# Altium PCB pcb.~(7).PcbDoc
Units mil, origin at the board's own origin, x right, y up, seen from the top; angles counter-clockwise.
Board outline 2165 x 2075 mil, 2 copper layers (Top Layer, Bottom Layer); 12 components, 10 nets, 37 pads, 0 vias.
Unrouted connection lines stored in the file: 25.
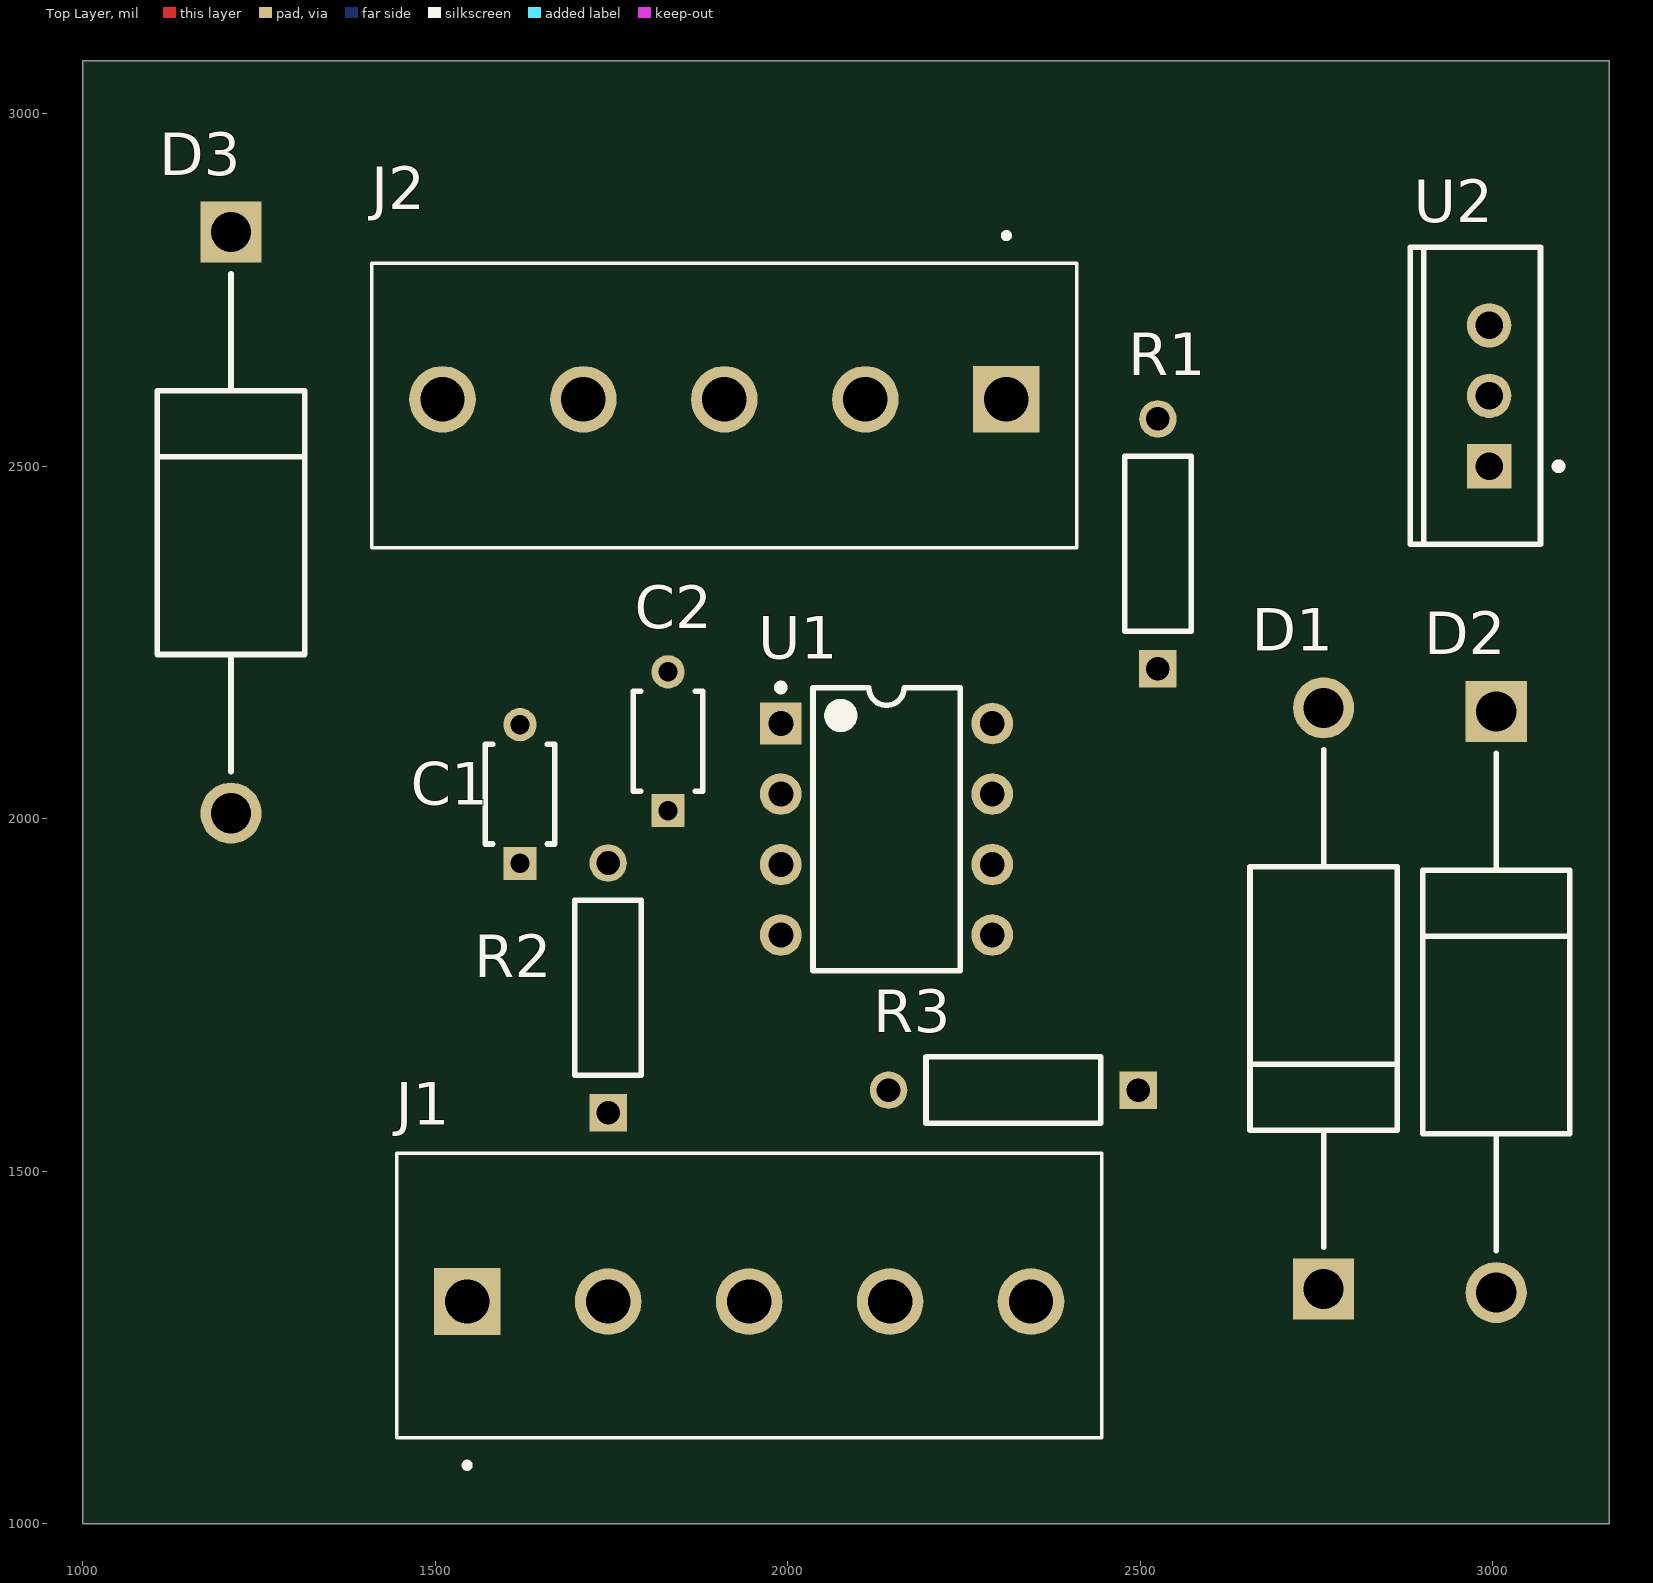
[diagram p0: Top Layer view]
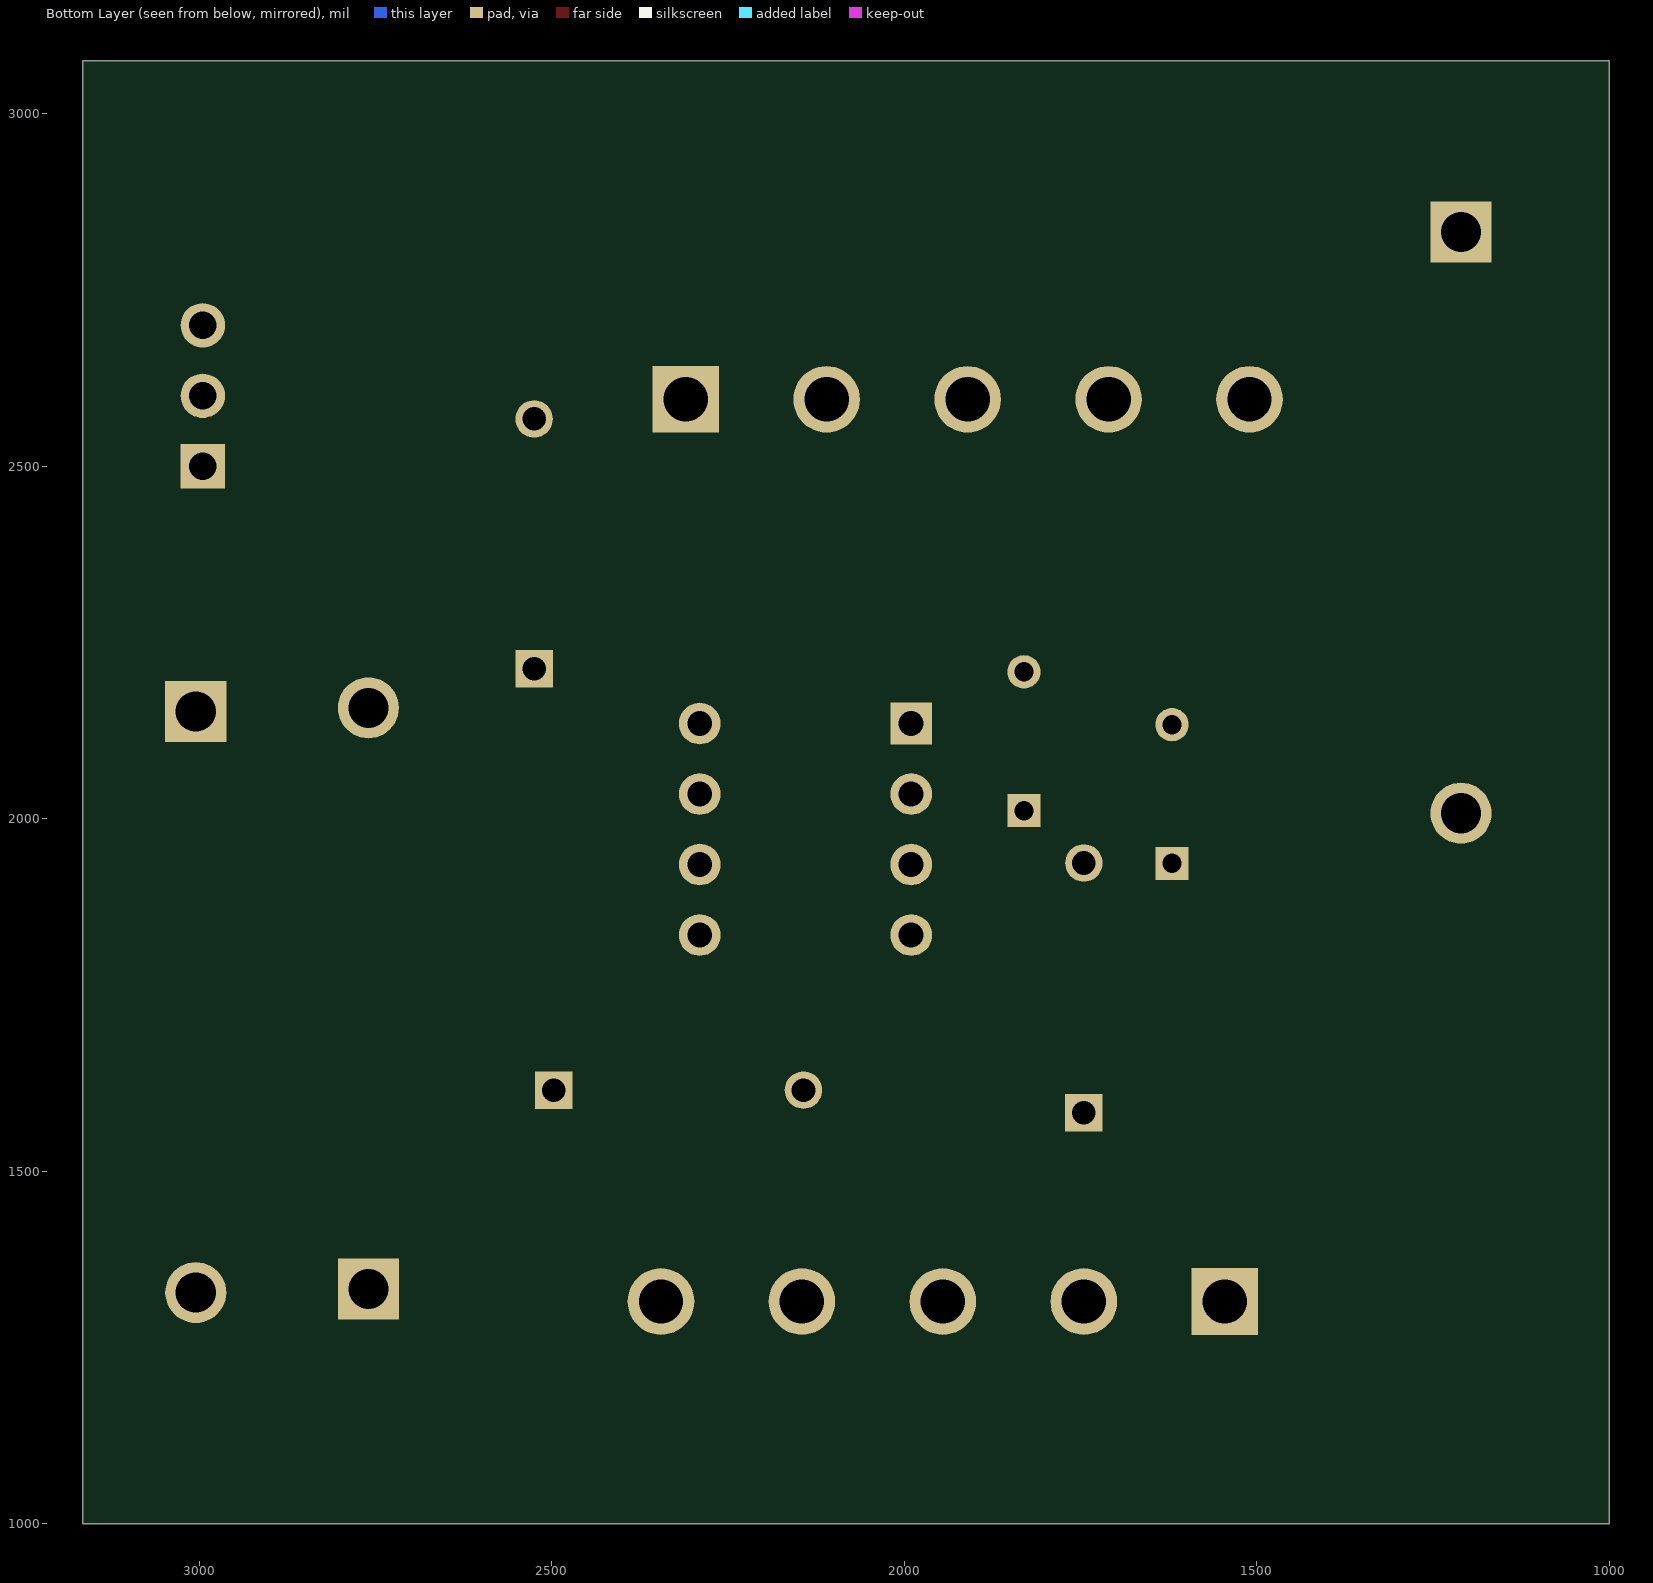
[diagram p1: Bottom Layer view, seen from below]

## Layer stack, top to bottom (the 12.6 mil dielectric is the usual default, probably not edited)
Top Solder: solder mask 0.4, Solder Resist, Dk 3.5
Top Layer: signal copper 1.4
Dielectric 1: dielectric 12.6, FR-4, Dk 4.8
Bottom Layer: signal copper 1.4
Bottom Solder: solder mask 0.4, Solder Resist, Dk 3.5

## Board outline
1000,1000 3165,1000 3165,3075 1000,3075

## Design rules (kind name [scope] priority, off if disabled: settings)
Clearance [All] p1: gap=10 ignorepadtopadclearanceinfootprint=FALSE except(0: Arc-Hole Track-Hole SMDPad-Hole THPad-Hole Via-Hole Fill-Hole Poly-Hole Region-Hole Text-Hole)
PolygonConnect [All] p1: connectstyle=Relief reliefconductorwidth=10 reliefentries=4 polygonreliefangle="90 Angle" airgapwidth=10
RoutingVias [All] p1: holewidth=30 width=50 viastyle="Through Hole" minholewidth=26 minwidth=36 maxholewidth=50 maxwidth=70
SolderMaskExpansion [All] p1: expansion=4 istentingtop=FALSE
Width [All] p1: maxlimit=50 minlimit=15 preferedwidth=35
30 further rules are at their usual default settings.

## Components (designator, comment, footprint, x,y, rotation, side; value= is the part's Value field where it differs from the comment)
C1 "RCER71H103K0K1H03B" FP-RCE0K1-MFG 1620,2035 r90 top
C2 "RCER71H103K0K1H03B" FP-RCE0K1-MFG 1830,2110 r90 top
D1 "1N5408G-T" FP-DO-201AD-MFG 2760,1745 r90 top
D2 "1N5408G-T" FP-DO-201AD-MFG 3005,1740 r270 top
D3 "1N5408G-T" FP-DO-201AD-MFG 1210,2420 r270 top
J1 "TB007-508-05BE" CUI_TB007-508-05BE 1545,1315 r0 top
J2 "TB007-508-05BE" CUI_TB007-508-05BE 2310,2595 r180 top
R1 "MFR-25FBF52-1K" RESA60-630X240 2525,2390 r90 top
R2 "MFR-25FBF52-1K" RESA60-630X240 1745,1760 r90 top
R3 "MFR-25FBF52-1K" RESA60-630X240 2320,1615 r180 top
U1 "NE555P" P0008A 2140,1985 r0 top
U2 "LM395T/NOPB" NDE0003A 2995,2600 r90 top

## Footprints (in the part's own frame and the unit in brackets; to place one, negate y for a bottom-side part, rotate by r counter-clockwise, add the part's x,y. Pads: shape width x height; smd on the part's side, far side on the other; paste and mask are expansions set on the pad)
CUI_TB007-508-05BE [mm]
  rect 2.4x2.4 hole 1.6: 1(0,0)
  round 2.4 hole 1.6: 2(5.08,0) 3(10.16,0) 4(15.24,0) 5(20.32,0)
  silkscreen extent -2.54,-6 22.86,5.35
FP-DO-201AD-MFG [mm]
  rect 2.2x2.2 hole 1.45 paste-1000 mask+0: 1(-10.47,0)
  round 2.2 hole 1.45 paste-1000 mask+0: 2(10.47,0)
  silkscreen extent -8.97,-2.65 8.97,2.65, body extent -11.67,-2.75 11.67,2.75, height 0.25
FP-RCE0K1-MFG [mm]
  rect 1.2x1.2 hole 0.7 paste-1000 mask+0: 1(-2.5,0)
  round 1.2 hole 0.7 paste-1000 mask+0: 2(2.5,0)
  silkscreen extent -1.8,-1.25 1.8,1.25, body extent -3.2,-1.35 3.2,1.35, height 0.25
NDE0003A [mm] "FM, 3-Leads, Body 10.7x4.7mm, Pitch 2.54mm"
  rect 1.6x1.6 hole 1: 1(-2.54,0)
  round 1.6 hole 1: 2(0,0) 3(2.54,0)
  silkscreen extent -5.35,-2.63 5.35,2.85, body extent -5.4,-1.9 5.4,2.9, height 19.4
P0008A [mm] "DIP, 8-Leads, Body 10.15x6.6mm, Pitch 2.54mm"
  rect 1.5x1.5 hole 0.9: 1(-3.81,3.81)
  round 1.5 hole 0.9: 2(-3.81,1.27) 3(-3.81,-1.27) 4(-3.81,-3.81) 5(3.81,-3.81) 6(3.81,-1.27) 7(3.81,1.27) 8(3.81,3.81)
  silkscreen extent -3.93,-5.1 2.65,5.23, body extent -3.95,-5.07 3.95,5.07, height 5.08
RESA60-630X240 [mm] "Axial Resistor, 2-Leads, Dia 2.4mm, Body Length 6.3mm"
  rect 1.35x1.35 hole 0.85: 1(-4.5,0)
  round 1.35 hole 0.85: 2(4.5,0)
  silkscreen extent -3.15,-1.2 3.15,1.2, body extent -3.15,-1.2 3.15,1.2, height 2.4

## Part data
C1 C2: library part CMP-06035-044411-1, "Cap Ceramic 10nF 50V X7R ±10% Radial 5mm +125°C Automotive Bulk", Capacitance=10nF, Case/Package=Radial, Dielectric=X7R, Max Operating Temperature=125°C, Min Operating Temperature=-55°C, Package Quantity=500, Ratings=AEC-Q200, Resistor Type=Ceramic, Tolerance=10%, Voltage Rating=50V
D1 D2 D3: library part CMP-12791-000058-1, "DIODE GEN PURP 1KV 3A DO201AD", Average Rectified Current=3A, Capacitance=40pF, Case/Package=DO-201AD, Forward Voltage=1.1V, Max Operating Temperature=150°C, Max Repetitive Reverse Voltage (Vrrm)=1kV, Max Reverse Current=5uA, Max Surge Current=125A, Min Operating Temperature=-65°C, Package Quantity=1200
J1 J2: Package=None
R1 R2 R3: library part CMP-1659-00075-1, "Axial Resistor, 1 KOhm, +/- 1%, 250 mW, -55 to 155 degC, 2-Pin THD, RoHS, Bulk", Case\Package=Axial, Max Operating Temperature="155 degC", Min Operating Temperature="-55 degC", Package Quantity=200, Power Rating="250 mW", Resistance="10 kohm", Tolerance=1%, Voltage Rating="250 V"
U1: library part CMP-2000-04954-1, "Precision Timer, 4.5 to 16 V, 0 to 70 degC, 8-Pin DIP, Pb-Free, Tube", Manufacturer=TexasInstruments, Maximum High Level Output Current=-200mA, Maximum Low Level Output Current=200mA, Operating Supply Voltage=5, Package=8PDIP, Package Description="8-Pin Double In-line Package, Body 9.59 x 6.35 mm, Pitch 2.54 mm", Package Reference=P8
U2: library part CMP-0063-01416-3, "Ultra Reliable Power Transistor, 3-pin TO-220, Pb-Free", Manufacturer="Texas Instruments", PackageTopMarking=NSUZXYTTE#*LM395T, PowerWise=N

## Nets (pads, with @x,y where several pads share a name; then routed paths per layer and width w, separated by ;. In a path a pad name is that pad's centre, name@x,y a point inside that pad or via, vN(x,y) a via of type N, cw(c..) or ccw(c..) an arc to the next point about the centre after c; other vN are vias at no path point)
GND: C1.2 C2.2 J1.1 J2.2 U1.1 U2.2 | length 12
  Top Layer w50: J2.2@2110,2582.96 J2.2
LED_IN: J1.2 R2.1
NetC2_1: C2.1 J1.3 U1.2 U1.6
NetD1_1: D1.1 J1.4
NetD1_2: D1.2 D2.1 R1.1 U1.7
NetD2_2: D2.2 J1.5
NetD3_2: D3.2 J2.5 U2.3
NetR2_2: R2.2 R3.2 U1.3
NetR3_1: R3.1 U2.1
VCC: C1.1 D3.1 J2.1 J2.4 R1.2 U1.4 U1.8
pads on no net: J2.3 U1.5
